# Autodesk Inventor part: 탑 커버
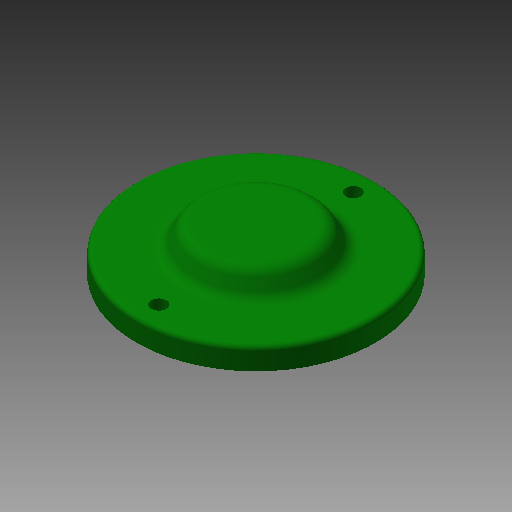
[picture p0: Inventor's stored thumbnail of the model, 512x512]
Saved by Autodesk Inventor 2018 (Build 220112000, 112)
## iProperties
Created: 2017-05
Part Number: 탑 커버
Material: 알루미늄 6061
Document SubType Name: Modeling
Designer: mduedu
Density: 1 g/cm^3
Appearance: 진녹색
Author: mduedu
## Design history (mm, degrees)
sketch "스케치1"
  geometry: C1 r 27 at (0, 0); 1 further point
  constraints: 1 centre point, 1 coincident
  dimensions: "d31" = 54 diameter of C1
extrude "돌출1" new body sketch "스케치1" distance "d2" = 5; taper "d3" = 0 deg
sketch "스케치2"
  geometry: C1 r 15 at (0, 0); 1 further point
  constraints: 1 centre point, 1 coincident
  dimensions: "d5" = 30 diameter of C1
extrude "돌출2" join sketch "스케치2" distance "d6" = 5; taper "d7" = -30 deg
sketch "스케치3"
  geometry: C1 r 16 at (0, 0); 1 further point
  constraints: 1 centre point, 1 coincident
  dimensions: "d32" = 32 diameter of C1
extrude "돌출3" join sketch "스케치3" distance "d10" = 3; taper "d11" = 0 deg
sketch "스케치4"
  geometry: C1 r 16 at (0, 0) reference; C2 r 13 at (0, 0); 1 further point
  constraints: 1 centre point
  dimensions: "d33" = 3 radial gap between concentric circles of C2 C1
extrude "돌출4" cut sketch "스케치4" distance "d14" = 6; taper "d15" = 0 deg
chamfer "모따기1" distance "d16" = 1; stored, may be unused: second distance "d17" = 2, angle "d18" = 45 deg
fillet "모깎기3" dims "d19" = 3
fillet "모깎기4" dims "d20" = 1
fillet "모깎기5" dims "d21" = 1
sketch "스케치5" dims "d34" = 44
  geometry: C1 r 27 at (0, 0) reference; 2 further points
  constraints: 2 vertical alignment, 1 coincident, 2 other
hole "구멍2" sketch "스케치5" at (0, 22) diameter "d35" = 3.4; stored, may be unused: countersink angle "d39" = 90 deg, drill point angle "d41" = 118 deg; dims "d36" = 6, "d37" = 4, "d38" = 2, "d40" = 8
node "솔리드1"
pattern_circular "원형 패턴1" dims angle "d43" = 360 deg
node "투영된 루프2"
